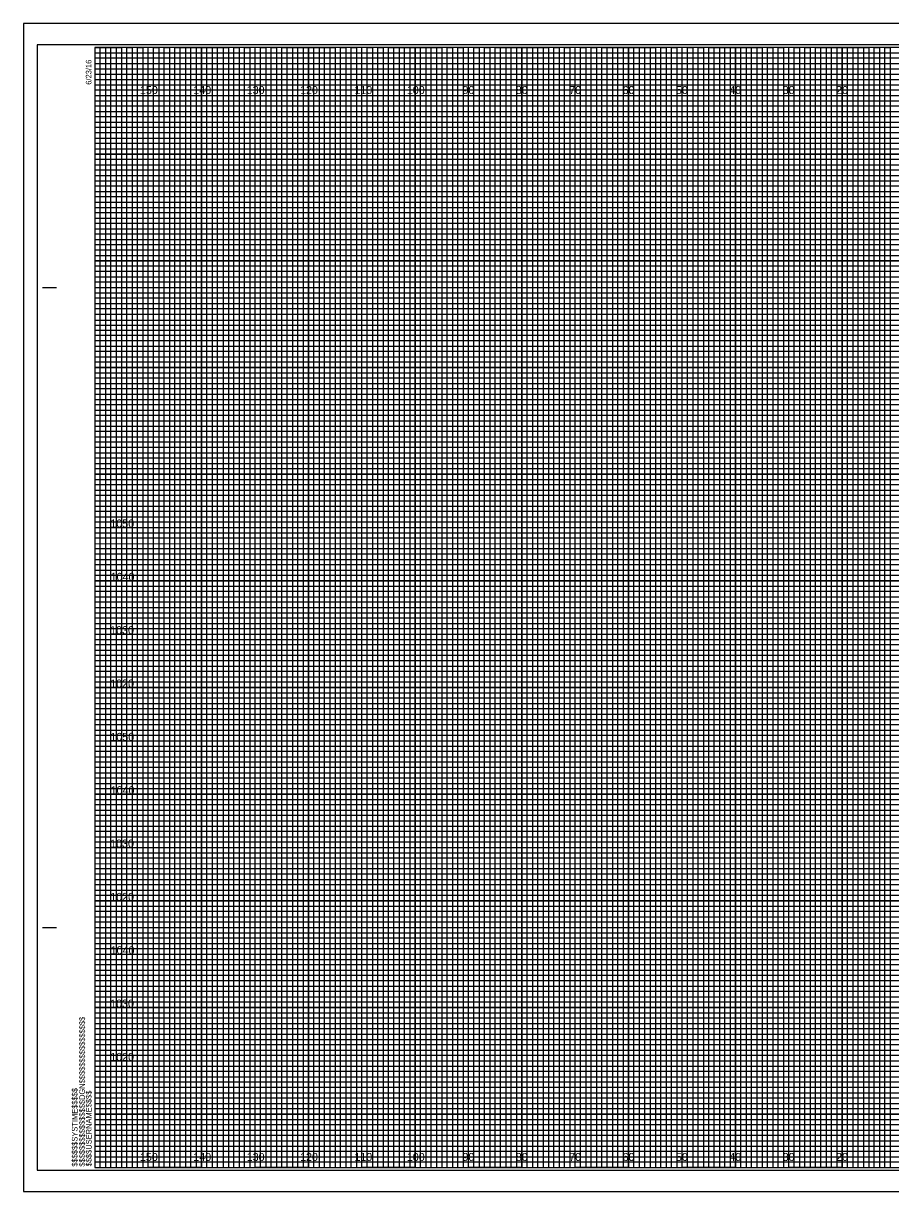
# Model space of a CAD drawing. Extents: x -13 to 323, y -5 to 215.
# Drawn here: x -13.4 to 149.1, y -4.5 to 214.5 of the extents above; entities that cross this region are included whole.
import ezdxf

# ---------------------------------------------------------------- set-up
doc = ezdxf.new("R2010")
doc.units = 0
for name, color, linetype in [('Prop XS Elevation Labels', 7, 'Continuous'), ('Prop XS Offset Labels', 7, 'Continuous'), ('Sheet Cross Section CELL', 7, 'Continuous'), ('Sheet Cross Section Grid Major CELL', 7, 'Continuous'), ('Sheet Cross Section Grid Middle CELL', 7, 'Continuous'), ('Sheet Cross Section Grid Minor 1 CELL', 7, 'Continuous'), ('Sheet Cross Section Grid Minor 2 CELL', 7, 'Continuous'), ('Sheet Cutting Line CELL', 7, 'Continuous'), ('Sheet DOT Grid CELL', 7, 'Continuous'), ('Sheet Plot Border Inside CELL', 7, 'Continuous'), ('Sheet Plot Border Outside CELL', 7, 'Continuous')]:
    doc.layers.add(name, color=color, linetype=linetype)

msp = doc.modelspace()

# ---------------------------------------------------------------- linework, layer by layer
at = {"layer": 'Sheet Cross Section CELL'}
for p, q in [((-9.8, 165), (-7.3, 165)), ((-9.7, 165), (-7.2, 165)), ((-9.8, 45), (-7.3, 45)), ((-9.7, 45), (-7.2, 45)), ((0, 0), (0, 0)), ((0, 0), (0, 0)), ((0, 0), (0, 0)), ((0, 0), (0, 0)), ((0, 0), (0, 0)), ((0, 0), (0, 0)), ((0, 0), (0, 0))]:
    msp.add_line(p, q, dxfattribs=at)
msp.add_lwpolyline([(320, 210), (0, 210), (0, 0), (320, 0)], close=True, dxfattribs=at)
at = {"layer": 'Sheet Cross Section Grid Major CELL'}
for p, q in [((10, 210), (0, 210)), ((10, 0), (10, 210)), ((30, 210), (20, 210)), ((20, 210), (20, 0)), ((30, 0), (30, 210)), ((50, 210), (40, 210)), ((40, 210), (40, 0)), ((50, 0), (50, 210)), ((70, 210), (60, 210)), ((60, 210), (60, 0)), ((70, 0), (70, 210)), ((90, 210), (80, 210)), ((80, 210), (80, 0)), ((90, 0), (90, 210)), ((110, 210), (100, 210)), ((100, 210), (100, 0)), ((110, 0), (110, 210)), ((130, 210), (120, 210)), ((120, 210), (120, 0)), ((130, 0), (130, 210)), ((150, 210), (140, 210)), ((140, 210), (140, 0)), ((20, 0), (10, 0)), ((40, 0), (30, 0)), ((60, 0), (50, 0)), ((80, 0), (70, 0)), ((100, 0), (90, 0)), ((120, 0), (110, 0)), ((140, 0), (130, 0))]:
    msp.add_line(p, q, dxfattribs=at)
for points in [[(0, 200), (320, 200), (320, 190), (0, 190)], [(0, 180), (320, 180), (320, 170), (0, 170)], [(0, 160), (320, 160), (320, 150), (0, 150)], [(0, 140), (320, 140), (320, 130), (0, 130)], [(0, 120), (320, 120), (320, 110), (0, 110)], [(0, 100), (320, 100), (320, 90), (0, 90)], [(0, 80), (320, 80), (320, 70), (0, 70)], [(0, 60), (320, 60), (320, 50), (0, 50)], [(0, 40), (320, 40), (320, 30), (0, 30)], [(0, 20), (320, 20), (320, 10), (0, 10)]]:
    msp.add_lwpolyline(points, dxfattribs=at)
at = {"layer": 'Sheet Cross Section Grid Middle CELL'}
for points in [[(0, 210), (5, 210), (5, 0), (15, 0), (15, 210), (25, 210), (25, 0), (35, 0), (35, 210), (45, 210), (45, 0), (55, 0), (55, 210), (65, 210), (65, 0), (75, 0), (75, 210), (85, 210), (85, 0), (95, 0), (95, 210), (105, 210), (105, 0), (115, 0), (115, 210), (125, 210), (125, 0), (135, 0), (135, 210), (145, 210), (145, 0), (155, 0)], [(0, 205), (275, 205)], [(0, 185), (320, 185), (320, 195), (0, 195)], [(0, 165), (320, 165), (320, 175), (0, 175)], [(0, 145), (320, 145), (320, 155), (0, 155)], [(0, 125), (320, 125), (320, 135), (0, 135)], [(0, 105), (320, 105), (320, 115), (0, 115)], [(0, 85), (320, 85), (320, 95), (0, 95)], [(0, 65), (320, 65), (320, 75), (0, 75)], [(0, 45), (320, 45), (320, 55), (0, 55)], [(0, 25), (320, 25), (320, 35), (0, 35)], [(0, 5), (320, 5), (320, 15), (0, 15)]]:
    msp.add_lwpolyline(points, dxfattribs=at)
at = {"layer": 'Sheet Cross Section Grid Minor 1 CELL'}
for p, q in [((0, 209), (260, 209)), ((260, 207.98), (0, 207.98)), ((0, 207.98), (0, 207)), ((0, 207), (260, 207)), ((260, 205.89), (0, 205.89)), ((0, 205.89), (0, 204)), ((0, 204), (320, 204))]:
    msp.add_line(p, q, dxfattribs=at)
for points in [[(0, 203), (270, 203), (320, 203), (320, 202), (0, 202)], [(0, 201), (320, 201), (320, 199), (0, 199)], [(0, 198), (320, 198), (320, 197), (0, 196.98)], [(0, 196), (320, 196), (320, 194), (0, 194)], [(0, 193), (320, 193), (320, 192), (0, 192)], [(0, 191), (320, 191), (320, 189), (0, 189)], [(0, 188), (320, 188), (320, 187), (0, 187)], [(0, 186), (320, 186), (320, 184), (0, 184)], [(0, 183), (320, 183), (320, 182), (0, 182)], [(0, 181), (320, 181), (320, 179), (0, 179)], [(0, 178), (320, 178), (320, 177), (0, 177)], [(0, 176), (320, 176), (320, 173.95), (320, 173), (320, 172), (0, 172)], [(0, 174), (320, 174), (320, 173), (0, 173)], [(0, 171), (320, 171), (320, 169), (0, 169.03)], [(0, 169.03), (320, 169), (320, 168), (0, 168)], [(0, 167), (320, 167), (320, 166), (0, 166)], [(0, 164), (320, 164), (320, 163), (0, 163)], [(0, 162), (320, 162), (320, 161), (0, 161)], [(-0.07, 158.89), (320, 158.89), (320, 157.88), (-0.07, 157.88)], [(0, 157), (320, 157), (320, 156), (0, 156)], [(0, 154), (320, 154), (320, 153), (0, 153)], [(0, 152), (320, 152), (320, 151), (0, 151)], [(0, 149), (320, 149), (320, 148), (0, 148)], [(0, 147), (320, 147), (320, 146), (0, 146)], [(0, 144), (320, 144), (320, 143), (0, 143)], [(0, 142), (320, 142), (320, 141), (0, 141)], [(0, 139), (320, 139), (319.99, 137.98), (0, 138)], [(0, 137), (320, 137), (320, 136), (0, 136)], [(0, 134), (320, 134), (320, 133), (0, 133)], [(0, 132), (320, 132), (320, 131), (0, 131)], [(0, 129), (320, 129), (320, 128), (0, 128)], [(0, 127), (320, 127), (320, 126), (0, 126)], [(0, 124), (320, 124), (320, 123), (0, 123)], [(0, 122), (320, 122), (320, 121), (0, 121)], [(0, 119), (320, 119), (320, 118), (0, 118)], [(0, 116.99), (320.07, 116.91), (320, 116), (0, 116)], [(0, 114), (320, 114), (320, 113), (0, 113)], [(0, 112), (320, 112), (320, 111), (0, 111)], [(0, 109), (320, 109), (320, 108), (0, 108)], [(0, 107), (320, 107), (320, 106), (0, 106)], [(0, 104), (320, 104), (320, 103), (0, 103)], [(0, 102), (320, 102), (320, 101), (0, 101)], [(0, 99), (320, 99), (320, 98), (0, 98)], [(0, 97), (320, 97), (320, 96), (0, 96)], [(0, 94), (320, 94), (320, 93), (0, 93)], [(0, 92), (320, 92), (320, 91), (0, 91)], [(0, 89), (320, 89), (320, 88), (0, 88)], [(0, 87), (320, 87), (320, 86), (0, 86)], [(0, 84), (320, 84), (320, 83), (0, 83)], [(0, 82), (320, 82), (320, 81), (0, 81)], [(0, 79), (320, 79), (319.99, 77.98), (0, 78)], [(0, 77), (320, 77), (320, 76), (0, 76)], [(0, 74), (320, 74), (320, 73), (0, 73)], [(0, 72), (320, 72), (320, 71), (0, 71)], [(0, 69), (320, 69), (320, 68), (0, 68)], [(0, 67), (320, 67), (320, 66), (0, 66)], [(0, 64), (320, 64), (320, 63), (0, 63)], [(0, 62), (320, 62), (320, 61), (0, 61)], [(0, 59), (320, 59), (320, 58), (0, 58)], [(0, 56.99), (320.07, 56.91), (320, 56), (0, 56)], [(0, 54), (320, 54), (320, 53), (0, 53)], [(0, 52), (320, 52), (320, 51), (0, 51)], [(0, 49), (320, 49), (320, 48), (0, 48)], [(0, 47), (320, 47), (320, 46), (0, 46)], [(0, 44), (320, 44), (320, 43), (0, 43)], [(0, 42), (320, 42), (320, 41), (0, 41)], [(0, 39), (320, 39), (320, 38), (0, 38)], [(0, 37), (320, 37), (320, 36), (0, 36)], [(0, 34), (320, 34), (320, 33), (0, 33)], [(0, 32), (320, 32), (320, 31), (0, 31)], [(0, 29), (320, 29), (320, 28), (0, 28)], [(0, 27), (320, 27), (320, 26), (0, 26)], [(0, 24), (320, 24), (320, 23), (0, 23)], [(0, 22), (320, 22), (320, 21), (0, 21)], [(0, 19), (320, 19), (320, 18), (0, 18)], [(0, 17), (320, 17), (320, 16), (0, 16)], [(0, 14), (320, 14), (320, 13), (0, 13)], [(0, 12), (320, 12), (320, 11), (0, 11)], [(0, 9), (320, 9), (320, 8), (0, 8)], [(0, 7), (320, 7), (320, 6), (0, 6)], [(0, 4), (320, 4), (320, 3), (0, 3)], [(0, 2), (320, 2), (320, 1), (0, 1)]]:
    msp.add_lwpolyline(points, dxfattribs=at)
at = {"layer": 'Sheet Cross Section Grid Minor 2 CELL'}
for points in [[(0, 0), (1, 0), (1, 210), (2, 210), (2, 0)], [(2, 0), (3, 0), (3, 210), (4, 210), (4, 0)], [(5, 0), (6, 0), (6, 210), (7, 210), (7, 0)], [(7, 0), (8, 0), (8, 210), (9, 210), (9, 0)], [(10, 0), (11, 0), (11, 210), (12, 210), (12, 0)], [(12, 0), (13, 0), (13, 210), (14, 210), (14, 0)], [(15, 0), (16, 0), (16, 210), (17, 210), (17, 0)], [(17, 0), (18, 0), (18, 210), (19, 210), (19, 0)], [(20, 0), (21, 0), (21, 210), (22, 210), (22, 0)], [(22, 0), (23, 0), (23, 210), (24, 210), (24, 0)], [(25, 0), (26, 0), (26, 210), (27, 210), (27, 0)], [(27, 0), (28, 0), (28, 210), (29, 210), (29, 0)], [(30, 0), (31, 0), (31, 210), (32, 210), (32, 0)], [(32, 0), (33, 0), (33, 210), (34, 210), (34, 0)], [(35, 0), (36, 0), (36, 210), (37, 210), (37, 0)], [(37, 0), (38, 0), (38, 210), (39, 210), (39, 0)], [(40, 0), (41, 0), (41, 210), (42, 210), (42, 0)], [(42, 0), (43, 0), (43, 210), (44, 210), (44, 0)], [(45, 0), (46, 0), (46, 210), (47, 210), (47, 0)], [(47, 0), (48, 0), (48, 210), (49, 210), (49, 0)], [(50, 0), (51, 0), (51, 210), (52, 210), (52, 0)], [(52, 0), (53, 0), (53, 210), (54, 210), (54, 0)], [(55, 0), (56, 0), (56, 210), (57, 210), (57, 0)], [(57, 0), (58, 0), (58, 210), (59, 210), (59, 0)], [(60, 0), (61, 0), (61, 210), (62, 210), (62, 0)], [(62, 0), (63, 0), (63, 210), (64, 210), (64, 0)], [(65, 0), (66, 0), (66, 210), (67, 210), (67, 0)], [(67, 0), (68, 0), (68, 210), (69, 210), (69, 0)], [(70, 0), (71, 0), (71, 210), (72, 210), (72, 0)], [(72, 0), (73, 0), (73, 210), (74, 210), (74, 0)], [(75, 0), (76, 0), (76, 210), (77, 210), (77, 0)], [(77, 0), (78, 0), (78, 210), (79, 210), (79, 0)], [(80, 0), (81, 0), (81, 210), (82, 210), (82, 0)], [(82, 0), (83, 0), (83, 210), (84, 210), (84, 0)], [(85, 0), (86, 0), (86, 210), (87, 210), (87, 0)], [(87, 0), (88, 0), (88, 210), (89, 210), (89, 0)], [(90, 0), (91, 0), (91, 210), (92, 210), (92, 0)], [(92, 0), (93, 0), (93, 210), (94, 210), (94, 0)], [(95, 0), (96, 0), (96, 210), (97, 210), (97, 0)], [(97, 0), (98, 0), (98, 210), (99, 210), (99, 0)], [(100, 0), (101, 0), (101, 210), (102, 210), (102, 0)], [(102, 0), (103, 0), (103, 210), (104, 210), (104, 0)], [(105, 0), (106, 0), (106, 210), (107, 210), (107, 0)], [(107, 0), (108, 0), (108, 210), (109, 210), (109, 0)], [(110, 0), (111, 0), (111, 210), (112, 210), (112, 0)], [(112, 0), (113, 0), (113, 210), (114, 210), (114, 0)], [(115, 0), (116, 0), (116, 210), (117, 210), (117, 0)], [(117, 0), (118, 0), (118, 210), (119, 210), (119, 0)], [(120, 0), (121, 0), (121, 210), (122, 210), (122, 0)], [(122, 0), (123, 0), (123, 210), (124, 210), (124, 0)], [(125, 0), (126, 0), (126, 210), (127, 210), (127, 0)], [(127, 0), (128, 0), (128, 210), (129, 210), (129, 0)], [(130, 0), (131, 0), (131, 210), (132, 210), (132, 0)], [(132, 0), (133, 0), (133, 210), (134, 210), (134, 0)], [(135, 0), (136, 0), (136, 210), (137, 210), (137, 0)], [(137, 0), (138, 0), (138, 210), (139, 210), (139, 0)], [(140, 0), (141, 0), (141, 210), (142, 210), (142, 0)], [(142, 0), (143, 0), (143, 210), (144, 210), (144, 0)], [(145, 0), (146, 0), (146, 210), (147, 210), (147, 0)], [(147, 0), (148, 0), (148, 210), (149, 210), (149, 0)]]:
    msp.add_lwpolyline(points, dxfattribs=at)
at = {"layer": 'Sheet Cutting Line CELL'}
for p, q in [((323.3, 214.5), (-13.4, 214.5)), ((-13.4, 214.5), (-13.4, -4.5)), ((-13.4, -4.5), (323.3, -4.5))]:
    msp.add_line(p, q, dxfattribs=at)
at = {"layer": 'Sheet DOT Grid CELL'}
for p, q in [((10, 0), (10, 210)), ((20, 0), (20, 210)), ((30, 0), (30, 210)), ((40, 0), (40, 210)), ((50, 0), (50, 210)), ((60, 0), (60, 210)), ((70, 0), (70, 210)), ((80, 0), (80, 210)), ((90, 0), (90, 210)), ((100, 0), (100, 210)), ((110, 0), (110, 210)), ((120, 0), (120, 210)), ((130, 0), (130, 210)), ((140, 0), (140, 210)), ((0, 200), (320, 200)), ((0, 190), (320, 190)), ((0, 180), (320, 180)), ((0, 170), (320, 170)), ((0, 160), (320, 160)), ((0, 150), (320, 150)), ((0, 140), (320, 140)), ((0, 130), (320, 130)), ((0, 120), (320, 120)), ((0, 110), (320, 110)), ((0, 100), (320, 100)), ((0, 90), (320, 90)), ((0, 80), (320, 80)), ((0, 70), (320, 70)), ((0, 60), (320, 60)), ((0, 50), (320, 50)), ((0, 40), (320, 40)), ((0, 30), (320, 30)), ((0, 20), (320, 20)), ((0, 10), (320, 10))]:
    msp.add_line(p, q, dxfattribs=at)
at = {"layer": 'Sheet Plot Border Inside CELL'}
msp.add_lwpolyline([(-10.8, -0.5), (322.4, -0.5), (322.4, 210.5), (-10.8, 210.5)], close=True, dxfattribs=at)
at = {"layer": 'Sheet Plot Border Outside CELL'}
msp.add_lwpolyline([(-13.4, -4.5), (323.3, -4.5), (323.3, 214.5), (-13.4, 214.5)], close=True, dxfattribs=at)

# ---------------------------------------------------------------- texts
at = {"layer": 'Prop XS Elevation Labels'}
for s, p in [('1050', (2.9, 120)), ('1040', (2.95, 110)), ('1030', (2.86, 100)), ('1020', (2.87, 90)), ('1050', (2.9, 80)), ('1040', (2.95, 70)), ('1030', (2.86, 60)), ('1020', (2.87, 50)), ('1040', (2.95, 40)), ('1030', (2.86, 30)), ('1020', (2.87, 20))]:
    msp.add_text(s, height=1.5, dxfattribs=at).set_placement(p)
at = {"layer": 'Prop XS Offset Labels'}
for s, p in [('150', (8.44, 201.25)), ('140', (18.44, 201.25)), ('130', (28.44, 201.25)), ('120', (38.44, 201.25)), ('110', (48.62, 201.25)), ('100', (58.44, 201.25)), ('90', (68.86, 201.25)), ('80', (78.86, 201.25)), ('70', (88.86, 201.25)), ('60', (98.86, 201.25)), ('50', (108.86, 201.25)), ('40', (118.86, 201.25)), ('30', (128.86, 201.25)), ('20', (138.86, 201.25)), ('150', (8.44, 1.25)), ('140', (18.44, 1.25)), ('130', (28.44, 1.25)), ('120', (38.44, 1.25)), ('110', (48.62, 1.25)), ('100', (58.44, 1.25)), ('90', (68.86, 1.25)), ('80', (78.86, 1.25)), ('70', (88.86, 1.25)), ('60', (98.86, 1.25)), ('50', (108.86, 1.25)), ('40', (118.86, 1.25)), ('30', (128.86, 1.25)), ('20', (138.86, 1.25))]:
    msp.add_text(s, height=1.5, dxfattribs=at).set_placement(p)
at = {"layer": 'Sheet Cross Section CELL'}
for s, p in [('6/23/16', (-0.65, 203)), ('$$$$$$$$$$$$$$$$DGN$$$$$$$$$$$$$$$$', (-1.88, 0.18)), ('$$$$$$SYSTIME$$$$$', (-3.26, 0.18)), ('$$$$USERNAME$$$$', (-0.62, 0.23))]:
    msp.add_text(s, height=1.05, rotation=90, dxfattribs=at).set_placement(p)

doc.saveas('drawing.dxf')
